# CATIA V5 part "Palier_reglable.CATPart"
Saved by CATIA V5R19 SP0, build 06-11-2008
Part number: Palier_reglable
Bounding box of the stored display mesh (mm): x 0 to 100, y 0 to 212, z -8 to 76
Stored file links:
  G:\EU_thinkMotion\CFAO_2010\MMS_groupe1\MMS_groupe1\OK\vduret\vduret\CATIA\Palier_reglable.CATPart
  F:\CFAO TP\Machine_de_coupe.CATProduct
  G:\EU_thinkMotion\CFAO_2010\MMS_groupe1\MMS_groupe1\OK\vduret\vduret\CATIA\Axe_outil_g.CATPart
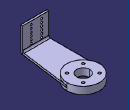
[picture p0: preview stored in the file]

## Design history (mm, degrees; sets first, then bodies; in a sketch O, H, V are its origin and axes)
External parameters (linked from other documents)
  External.Hauteur_bras = 200 mm
Body1 (main body)
  Sketch1 on yz-plane, origin (0, 0, 0), H (0, 1, 0), V (0, 0, 1)
    line L1 (0, 76) -> (0, 0)
    line L2 (0, 0) -> (212, 0)
    line L3 (212, 0) -> (212, 6)
    line L4 (212, 6) -> (6, 6)
    line L5 (6, 6) -> (6, 76)
    line L6 (6, 76) -> (0, 76)
    reference intersected line E1 through (0, 0) direction (0, 1) from zx-plane
    length L5 = 70
    length L3 = 6
    length L6 = 6
    length L2 = 212 {= External.Hauteur_bras +12mm}
    vertical: L1 V, L3 V, L5 V
    horizontal: L2 H, L4 H, L6 H
    coincidence: L2 H, E1 L1
  Pad1: profile Sketch1, direction (1, 0, 0), length 100
  Sketch2 on face of Pad1 from Sketch1.L4, origin (0, 0, 6), H (1, 0, 0), V (0, 1, 0)
    circle A1 centre (50, 162) radius 25
    point P1 (50, 162)
    reference projected line E1 (0, 250) -> (0, 6) from edge [start face of Pad1 | face of Pad1 from Sketch1.L4]
    reference projected line E2 (0, 0) -> (70, 0) from edge [face of Pad1 from Sketch1.L2 | face of Pad1 from Sketch1.L1]
    radius A1 = 25
    distance E1 P1 = 50
    distance E2 P1 = 162 {= External.Hauteur_bras -38mm}
  Pocket1: profile Sketch2, direction (0, 0, -1), through (limit type 6)
  Sketch3 on face of Pad1 from Sketch1.L5, origin (0, 6, 0), H (-1, 0, 0), V (0, 0, 1)
    construction line L1 (-37.5, 100) -> (-37.5, -40)
    reference projected line E1 (-100, 6) -> (-100, 76) from edge [face of Pad1 from Sketch1.L5 | end face of Pad1]
    construction line L2 (-120, 41) -> (60, 41)
    reference projected line E2 (0, 76) -> (-100, 76) from edge [face of Pad1 from Sketch1.L6 | face of Pad1 from Sketch1.L5]
    circle A1 centre (-53.5, 46) radius 3
    point P5 (-53.5, 46)
    point P6 (-53.5, 56)
    circle A2 centre (-53.5, 56) radius 3
    point P7 (-53.5, 66)
    circle A3 centre (-53.5, 66) radius 3
    axis line L3 (-53.5, 17.2716) -> (-53.5, 107.2716)
    reference projected line E3 (0, 76) -> (-100, 76) from edge [face of Pad1 from Sketch1.L6 | face of Pad1 from Sketch1.L5]
    circle A4 centre (-53.5, 16) radius 3
    circle A5 centre (-53.5, 26) radius 3
    circle A6 centre (-53.5, 36) radius 3
    circle A7 centre (-21.5, 66) radius 3
    circle A8 centre (-21.5, 56) radius 3
    circle A9 centre (-21.5, 46) radius 3
    circle A10 centre (-21.5, 36) radius 3
    circle A11 centre (-21.5, 26) radius 3
    circle A12 centre (-21.5, 16) radius 3
    distance L1 E1 = 62.5
    distance L2 E2 = 35
    radius A1 = 3
    distance P5 L1 = 16
    distance P7 P6 = 10
    distance P6 P5 = 10
    distance P7 E3 = 10
    radius A3 = 3
    radius A2 = 3
    vertical: L1 V, L3 V
    horizontal: L2 H
    coincidence: P5 L3, P6 L3, P7 L3
    symmetry: A3 A4 L2, A2 A5 L2, A1 A6 L2, A3 A7 L1, A2 A8 L1, A1 A9 L1, A6 A10 L1, A5 A11 L1, A4 A12 L1
  Pocket2: profile Sketch3, direction (0, -1, 0), through (limit type 6)
  Fillet1: radius 50, on edge [face of Pad1 from Sketch1.L3 | end face of Pad1]; edge [start face of Pad1 | face of Pad1 from Sketch1.L3]
  Sketch4 on face of Pad1 from Sketch1.L2, origin (0, 0, 0), H (1, 0, 0), V (0, -1, 0)
    circle A1 centre (50, -162) radius 50
    point P1 (50, -162)
    reference projected arc E1 centre (50, -162) radius 50 from (50, -212) to (100, -162) ccw from edge [face of Pad1 from Sketch1.L2 | face of Fillet1]
    circle A2 centre (50, -162) radius 20
    circle A3 centre (25, -137) radius 4
    point P2 (25, -137)
    construction line L1 (50, -110) -> (50, -210)
    axis line L2 (-20, -162) -> (160, -162)
    circle A4 centre (75, -137) radius 4
    circle A5 centre (75, -187) radius 4
    circle A6 centre (25, -187) radius 4
    radius A2 = 20
    radius A3 = 4
    distance P2 L2 = 25
    distance P2 L1 = 25
    coincidence: A1 E1, L1 P1, L2 P1
    vertical: L1 V
    horizontal: L2 H
    symmetry: A3 A4 L1, A4 A5 L2, A3 A6 L2
  Pad2: profile Sketch4, direction (0, 0, -1), length 8, opposite side length 14
  Sketch5 on face of Pad1 from Sketch1.L2, origin (0, 0, 0), H (1, 0, 0), V (0, -1, 0)
    point P1 (80, 0)
    line L1 (80, 0) -> (80, -6)
    line L2 (80, -6) -> (100, -158.7404)
    line L3 (100, -158.7404) -> (100, 0)
    point P4 (100, 0)
    line L4 (100, 0) -> (80, 0)
    reference projected circle E1 centre (50, -162) radius 50 from edge [face of Pad2 from Sketch4.A1 | end face of Pad2]
    reference projected line E2 (100, 0) -> (100, -212) from edge [face of Pad1 from Sketch1.L2 | end face of Pad1]
    length L1 = 6
    length L4 = 20
    coincidence: P1 H, P4 H, L3 E2
    vertical: L1 V, L3 V
    horizontal: L4 H
    tangency: L2 E1
  Pocket3: profile Sketch5, direction (0, 0, 1), through (limit type 6)
  Fillet2: radius 5, on edge [face of Pad1 from Sketch1.L5 | face of Pad1 from Sketch1.L4]
  Fillet3: radius 5, on edge [face of Pad1 from Sketch1.L2 | face of Pad1 from Sketch1.L1]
